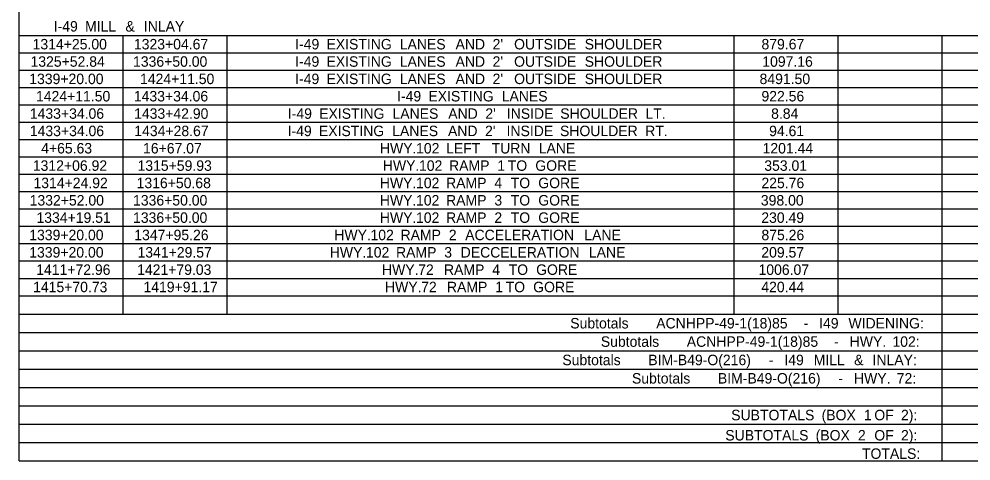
# Model space of a CAD drawing. Extents: x 1226567 to 1228151, y 151309 to 152305.
# Drawn here: x 1226566.8 to 1226930.3, y 151664.6 to 151833.3 of the extents above; entities that cross this region are included whole.
import ezdxf

# ---------------------------------------------------------------- set-up
doc = ezdxf.new("R2010")
doc.units = 0
doc.layers.add('R_Dimension', color=7, linetype='Continuous')

msp = doc.modelspace()

# ---------------------------------------------------------------- linework, layer by layer
at = {"layer": 'R_Dimension'}
for p, q in [((1226566.84, 151664.64), (1226566.84, 152254.68)), ((1226566.84, 151827.05), (1228150.79, 151827.05)), ((1226606.57, 151720.72), (1226606.57, 151827.05)), ((1226646.29, 151720.72), (1226646.29, 151827.05)), ((1226839.86, 151720.72), (1226839.86, 151827.05)), ((1226879.58, 151720.72), (1226879.58, 151827.05)), ((1226919.31, 151664.64), (1226919.31, 151827.05)), ((1226566.84, 151820.42), (1228150.79, 151820.42)), ((1226566.84, 151813.8), (1228150.79, 151813.8)), ((1226566.84, 151807.18), (1228150.79, 151807.18)), ((1226566.84, 151800.56), (1228150.79, 151800.56)), ((1226566.84, 151793.94), (1228150.79, 151793.94)), ((1226566.84, 151787.32), (1228150.79, 151787.32)), ((1226566.84, 151780.7), (1228150.79, 151780.7)), ((1226566.84, 151774.08), (1228150.79, 151774.08)), ((1226566.84, 151767.46), (1228150.79, 151767.46)), ((1226566.84, 151760.84), (1228150.79, 151760.84)), ((1226566.84, 151754.22), (1228150.79, 151754.22)), ((1226566.84, 151747.6), (1228150.79, 151747.6)), ((1226566.84, 151740.97), (1228150.79, 151740.97)), ((1226566.84, 151734.35), (1228150.79, 151734.35)), ((1226566.84, 151727.73), (1228150.79, 151727.73)), ((1226566.84, 151720.72), (1228150.79, 151720.72)), ((1226566.84, 151713.71), (1228150.79, 151713.71)), ((1226566.84, 151706.7), (1228150.79, 151706.7)), ((1226566.84, 151699.69), (1228150.79, 151699.69)), ((1226566.84, 151692.68), (1228150.79, 151692.68)), ((1226566.84, 151685.67), (1228150.79, 151685.67)), ((1226566.84, 151678.66), (1228150.79, 151678.66)), ((1226566.84, 151671.65), (1228150.79, 151671.65)), ((1226566.84, 151664.64), (1228150.79, 151664.64))]:
    msp.add_line(p, q, dxfattribs=at)

# ---------------------------------------------------------------- texts
for s, height, p in [('I-49', 3.994, (1226580.09, 151828.55)), (' MILL', 3.994, (1226590.56, 151828.55)), (' &', 3.994, (1226606, 151828.55)), (' INLAY', 3.994, (1226613.02, 151828.55)), ('1314+25.00', 3.994, (1226572.03, 151821.74)), ('1323+04.67', 3.994, (1226610.71, 151821.74)), ('I-49', 3.994, (1226672.28, 151821.74)), (' EXISTING', 3.994, (1226682.75, 151821.74)), (' LANES', 3.994, (1226710.74, 151821.74)), (' AND', 3.994, (1226732.04, 151821.74)), (" 2'", 3.994, (1226746.19, 151821.74)), (' OUTSIDE', 3.994, (1226754.4, 151821.74)), (' SHOULDER', 3.994, (1226781.35, 151821.74)), ('879.67', 3.994, (1226850.35, 151821.74)), ('1325+52.84', 3.994, (1226571.23, 151815.12)), ('1336+50.00', 3.994, (1226610.38, 151815.12)), ('I-49', 3.994, (1226672.28, 151815.12)), (' EXISTING', 3.994, (1226682.75, 151815.12)), (' LANES', 3.994, (1226710.74, 151815.12)), (' AND', 3.994, (1226732.04, 151815.12)), (" 2'", 3.994, (1226746.19, 151815.12)), (' OUTSIDE', 3.994, (1226754.4, 151815.12)), (' SHOULDER', 3.994, (1226781.35, 151815.12)), ('1097.16', 3.994, (1226850.65, 151815.12)), ('1339+20.00', 3.994, (1226570.74, 151808.5)), ('1424+11.50', 3.994, (1226613.05, 151808.5)), ('I-49', 3.994, (1226672.28, 151808.5)), (' EXISTING', 3.994, (1226682.75, 151808.5)), (' LANES', 3.994, (1226710.74, 151808.5)), (' AND', 3.994, (1226732.04, 151808.5)), (" 2'", 3.994, (1226746.19, 151808.5)), (' OUTSIDE', 3.994, (1226754.4, 151808.5)), (' SHOULDER', 3.994, (1226781.35, 151808.5)), ('8491.50', 3.994, (1226849.61, 151808.5)), ('1424+11.50', 3.994, (1226573.32, 151801.88)), ('1433+34.06', 3.994, (1226610.69, 151801.88)), ('I-49', 3.994, (1226711.2, 151801.88)), (' EXISTING', 3.994, (1226721.67, 151801.88)), (' LANES', 3.994, (1226749.67, 151801.88)), ('922.56', 3.994, (1226850.33, 151801.88)), ('1433+34.06', 3.994, (1226570.96, 151795.25)), ('1433+42.90', 3.994, (1226610.78, 151795.25)), ('I-49', 3.994, (1226669.49, 151795.25)), (' EXISTING', 3.994, (1226679.97, 151795.25)), (' LANES', 3.994, (1226707.96, 151795.25)), (' AND', 3.994, (1226729.25, 151795.25)), (" 2'", 3.994, (1226743.41, 151795.25)), (' INSIDE', 3.994, (1226751.62, 151795.25)), (' SHOULDER', 3.994, (1226772.03, 151795.25)), (' LT.', 3.994, (1226804.55, 151795.25)), ('8.84', 3.994, (1226854.03, 151795.25)), ('1433+34.06', 3.994, (1226570.96, 151788.63)), ('1434+28.67', 3.994, (1226610.86, 151788.63)), ('I-49', 3.994, (1226669.4, 151788.63)), (' EXISTING', 3.994, (1226679.87, 151788.63)), (' LANES', 3.994, (1226707.86, 151788.63)), (' AND', 3.994, (1226729.16, 151788.63)), (" 2'", 3.994, (1226743.31, 151788.63)), (' INSIDE', 3.994, (1226751.52, 151788.63)), (' SHOULDER', 3.994, (1226771.93, 151788.63)), (' RT.', 3.994, (1226804.46, 151788.63)), ('94.61', 3.994, (1226853.27, 151788.63)), ('4+65.63', 3.994, (1226575.29, 151782.01)), ('16+67.07', 3.994, (1226614.2, 151782.01)), ('HWY.', 3.994, (1226704.64, 151782.01)), (' 102', 3.994, (1226716.97, 151782.01)), (' LEFT', 3.994, (1226728.45, 151782.01)), (' TURN', 3.994, (1226745.81, 151782.01)), (' LANE', 3.994, (1226763.8, 151782.01)), ('1201.44', 3.994, (1226850.76, 151782.01)), ('1312+06.92', 3.994, (1226572.11, 151775.39)), ('1315+59.93', 3.994, (1226612.09, 151775.39)), ('HWY.', 3.994, (1226705.76, 151775.39)), (' 102', 3.994, (1226718.09, 151775.39)), (' RAMP', 3.994, (1226729.57, 151775.39)), (' 1', 3.994, (1226748, 151775.39)), (' TO', 3.994, (1226751.99, 151775.39)), (' GORE', 3.994, (1226762.5, 151775.39)), ('353.01', 3.994, (1226851.42, 151775.39)), ('1314+24.92', 3.994, (1226572.36, 151768.77)), ('1316+50.68', 3.994, (1226611.74, 151768.77)), ('HWY.', 3.994, (1226704.62, 151768.77)), (' 102', 3.994, (1226716.95, 151768.77)), (' RAMP', 3.994, (1226728.43, 151768.77)), (' 4', 3.994, (1226746.87, 151768.77)), (' TO', 3.994, (1226753.12, 151768.77)), (' GORE', 3.994, (1226763.63, 151768.77)), ('225.76', 3.994, (1226850.33, 151768.77)), ('1332+52.00', 3.994, (1226570.9, 151762.15)), ('1336+50.00', 3.994, (1226610.38, 151762.15)), ('HWY.', 3.994, (1226704.62, 151762.15)), (' 102', 3.994, (1226716.95, 151762.15)), (' RAMP', 3.994, (1226728.43, 151762.15)), (' 3', 3.994, (1226746.87, 151762.15)), (' TO', 3.994, (1226753.12, 151762.15)), (' GORE', 3.994, (1226763.63, 151762.15)), ('398.00', 3.994, (1226850.11, 151762.15)), ('1334+19.51', 3.994, (1226573.5, 151755.53)), ('1336+50.00', 3.994, (1226610.38, 151755.53)), ('HWY.', 3.994, (1226704.62, 151755.53)), (' 102', 3.994, (1226716.95, 151755.53)), (' RAMP', 3.994, (1226728.43, 151755.53)), (' 2', 3.994, (1226746.87, 151755.53)), (' TO', 3.994, (1226753.12, 151755.53)), (' GORE', 3.994, (1226763.63, 151755.53)), ('230.49', 3.994, (1226850.27, 151755.53)), ('1339+20.00', 3.994, (1226570.74, 151748.91)), ('1347+95.26', 3.994, (1226610.85, 151748.91)), ('HWY.', 3.994, (1226687.23, 151748.91)), (' 102', 3.994, (1226699.56, 151748.91)), (' RAMP', 3.994, (1226711.04, 151748.91)), (' 2', 3.994, (1226729.47, 151748.91)), (' ACCELERATION', 3.9945, (1226735.73, 151748.91)), (' LANE', 3.994, (1226781.21, 151748.91)), ('875.26', 3.994, (1226850.33, 151748.91)), ('1339+20.00', 3.994, (1226570.74, 151742.29)), ('1341+29.57', 3.994, (1226612.09, 151742.29)), ('HWY.', 3.994, (1226685.5, 151742.29)), (' 102', 3.994, (1226697.83, 151742.29)), (' RAMP', 3.994, (1226709.31, 151742.29)), (' 3', 3.994, (1226727.74, 151742.29)), (' DECCELERATION', 3.9945, (1226734, 151742.29)), (' LANE', 3.994, (1226782.94, 151742.29)), ('209.57', 3.994, (1226850.28, 151742.29)), ('1411+72.96', 3.994, (1226573.39, 151735.67)), ('1421+79.03', 3.994, (1226611.93, 151735.67)), ('HWY.', 3.994, (1226705.44, 151735.67)), (' 72', 3.994, (1226717.77, 151735.67)), (' RAMP', 3.994, (1226727.62, 151735.67)), (' 4', 3.994, (1226746.05, 151735.67)), (' TO', 3.994, (1226752.31, 151735.67)), (' GORE', 3.994, (1226762.81, 151735.67)), ('1006.07', 3.994, (1226849.21, 151735.67)), ('1415+70.73', 3.994, (1226572.21, 151729.05)), ('1419+91.17', 3.994, (1226614.35, 151729.05)), ('HWY.', 3.994, (1226706.58, 151729.05)), (' 72', 3.994, (1226718.9, 151729.05)), (' RAMP', 3.994, (1226728.75, 151729.05)), (' 1', 3.994, (1226747.18, 151729.05)), (' TO', 3.994, (1226751.17, 151729.05)), (' GORE', 3.994, (1226761.68, 151729.05)), ('420.44', 3.994, (1226850.28, 151729.05)), ('Subtotals', 3.994, (1226777.33, 151715.22)), (' ACNHPP-49-1(18)85', 3.9945, (1226808.66, 151715.22)), (' I49', 3.994, (1226870.87, 151715.22)), (' WIDENING:', 3.994, (1226882.07, 151715.22)), (' -', 3.994, (1226864.93, 151715.22)), ('Subtotals', 3.994, (1226789, 151708.21)), (' ACNHPP-49-1(18)85', 3.9945, (1226820.33, 151708.21)), (' HWY.', 3.994, (1226882.54, 151708.21)), (' 102:', 3.994, (1226898.87, 151708.21)), (' -', 3.994, (1226876.6, 151708.21)), ('Subtotals', 3.994, (1226774.31, 151701.2)), (' BIM-B49-O(216)', 3.9945, (1226805.64, 151701.2)), (' -', 3.994, (1226851.66, 151701.2)), (' I49', 3.994, (1226857.6, 151701.2)), (' MILL', 3.994, (1226868.8, 151701.2)), (' &', 3.994, (1226884.24, 151701.2)), (' INLAY:', 3.994, (1226891.26, 151701.2)), ('Subtotals', 3.994, (1226800.89, 151694.19)), (' BIM-B49-O(216)', 3.9945, (1226832.22, 151694.19)), (' -', 3.994, (1226878.23, 151694.19)), (' HWY.', 3.994, (1226884.18, 151694.19)), (' 72:', 3.994, (1226900.5, 151694.19)), ('SUBTOTALS', 3.994, (1226838.79, 151680.17)), (' (BOX', 3.994, (1226871.82, 151680.17)), (' 1', 3.994, (1226887.95, 151680.17)), (' OF', 3.994, (1226891.95, 151680.17)), (' 2):', 3.994, (1226902.14, 151680.17)), ('SUBTOTALS', 3.994, (1226836.53, 151672.45)), (' (BOX', 3.994, (1226869.55, 151672.45)), (' 2', 3.994, (1226885.69, 151672.45)), (' OF', 3.994, (1226891.95, 151672.45)), (' 2):', 3.994, (1226902.14, 151672.45)), ('TOTALS:', 3.994, (1226888.71, 151665.44))]:
    msp.add_text(s, height=height, dxfattribs=at).set_placement(p)

doc.saveas('drawing.dxf')
